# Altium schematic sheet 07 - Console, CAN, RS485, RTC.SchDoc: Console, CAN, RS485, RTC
size A3; PageSetup: Record=PageOptions¦CenterHorizontal=True¦CenterVertical=True¦PrintScale=0.70¦XCorrection=1.00¦YCorrection=1.00¦PrintKind=0¦BorderSize=5000000¦LeftOffset=0¦BottomOffset=0¦Orientation=2¦PaperLength=4200¦PaperWidth=2970¦Scale=100¦PaperSource=7¦PrintQuality=600¦MediaType=1¦DitherType=10¦PaperKind=A4¦PrintScaleMode=1; Author: Juan Anzola; SheetNumber: 7; SheetTotal: 20
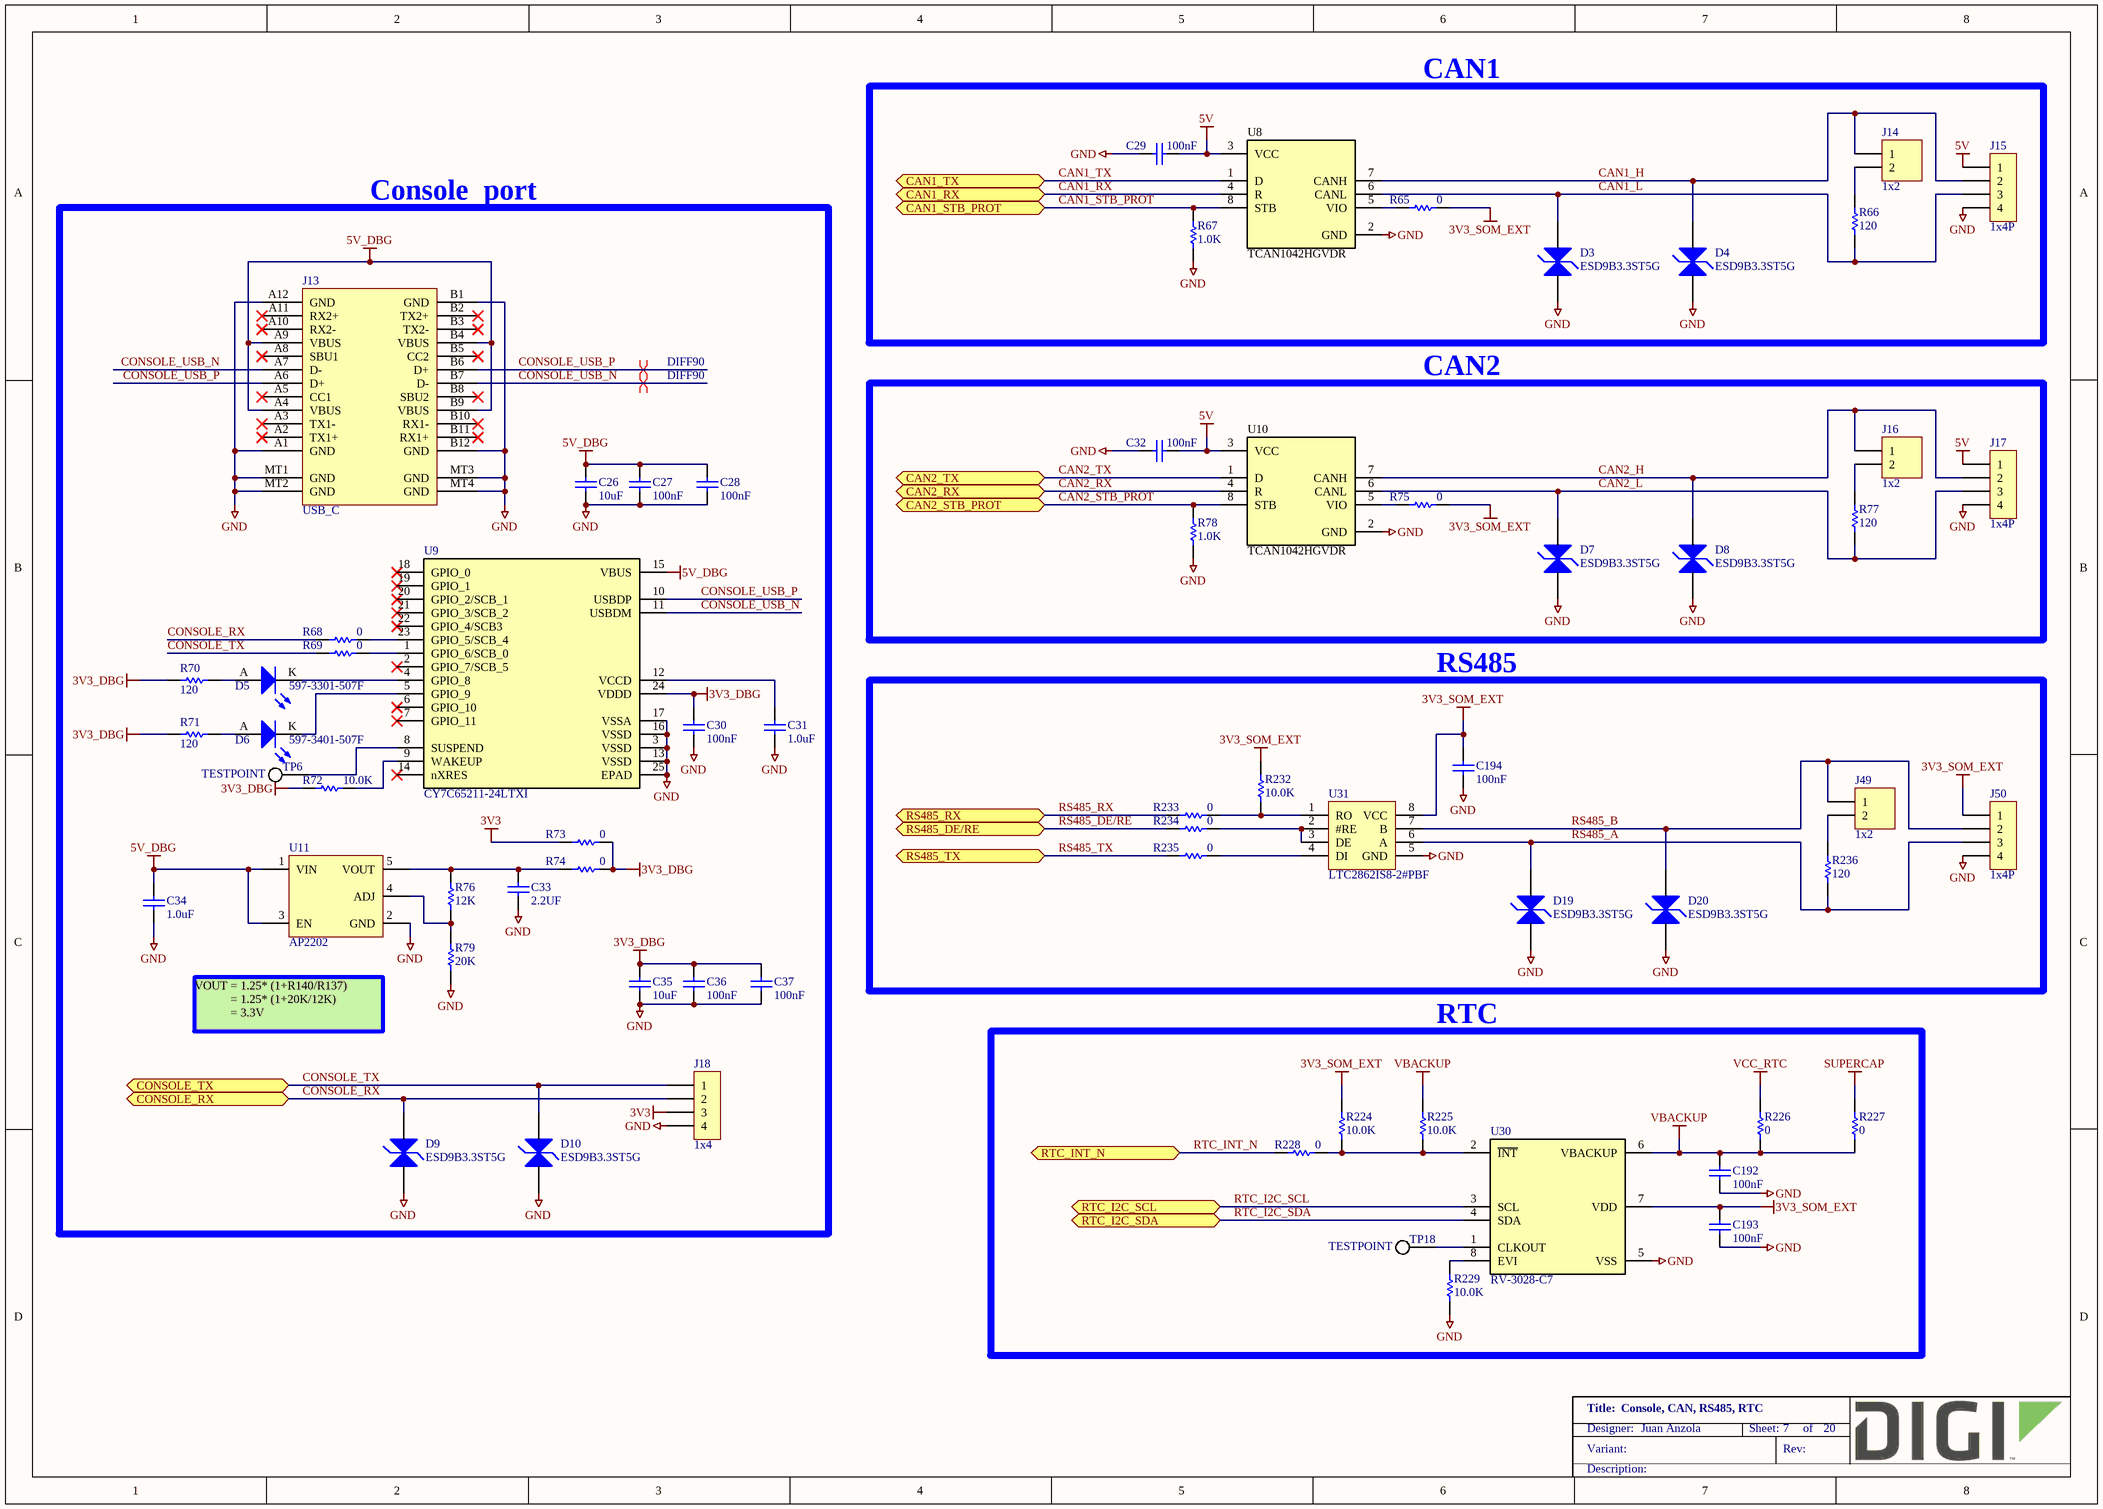
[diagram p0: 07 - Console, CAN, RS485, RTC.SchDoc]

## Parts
C26  10uF  [CAPC2013X135N]
C27  100nF  [CAPC1005X55N]
C28  100nF  [CAPC1005X55N]
C29  100nF  [CAPC1005X55N]
C30  100nF  [CAPC1005X55N]
C31  1.0uF  [CAPC1005X55N]
C32  100nF  [CAPC1005X55N]
C33  2.2UF  [CAPC1608X90N]
C34  1.0uF  [CAPC1005X55N]
C35  10uF  [CAPC2013X135N]
C36  100nF  [CAPC1005X55N]
C37  100nF  [CAPC1005X55N]
C192  100nF  [CAPC1005X55N]
C193  100nF  [CAPC1005X55N]
C194  100nF  [CAPC1005X55N]
D3  ESD9B3.3ST5G  [SODFL1006X43AN12]
D4  ESD9B3.3ST5G  [SODFL1006X43AN12]
D5  597-3301-507F  [LEDM3020X130N_GREEN]
D6  597-3401-507F  [LEDM3020X130N_YELLOW]
D7  ESD9B3.3ST5G  [SODFL1006X43AN12]
D8  ESD9B3.3ST5G  [SODFL1006X43AN12]
D9  ESD9B3.3ST5G  [SODFL1006X43AN12]
D10  ESD9B3.3ST5G  [SODFL1006X43AN12]
D19  ESD9B3.3ST5G  [SODFL1006X43AN12]
D20  ESD9B3.3ST5G  [SODFL1006X43AN12]
J13  USB_C  [MOLEX_201267-0005]
J14  1x2  [FCI_68002-102HLF]
J15  1x4P  [P4_STR_C2.54_H5.84]
J16  1x2  [FCI_68002-102HLF]
J17  1x4P  [P4_STR_C2.54_H5.84]
J18  1x4  [MOLEX_53047-0410]
J49  1x2  [FCI_68002-102HLF]
J50  1x4P  [P4_STR_C2.54_H5.84]
R65  0  [RESC1005X40N]
R66  120  [RESC1005X40N]
R67  1.0K  [RESC1005X40N]
R68  0  [RESC1005X40N]
R69  0  [RESC1005X40N]
R70  120  [RESC1005X40N]
R71  120  [RESC1005X40N]
R72  10.0K  [RESC1005X40N]
R73  0  [RESC1609X55N]
R74  0  [RESC1609X55N]
R75  0  [RESC1005X40N]
R76  12K  [RESC1609X55N]
R77  120  [RESC1005X40N]
R78  1.0K  [RESC1005X40N]
R79  20K  [RESC1609X55N]
R224  10.0K  [RESC1005X40N]
R225  10.0K  [RESC1005X40N]
R226  0  [RESC1005X40N]
R227  0  [RESC1005X40N]
R228  0  [RESC1005X40N]
R229  10.0K  [RESC1005X40N]
R232  10.0K  [RESC1005X40N]
R233  0  [RESC1005X40N]
R234  0  [RESC1005X40N]
R235  0  [RESC1005X40N]
R236  120  [RESC1005X40N]
TP6  TESTPOINT  [TP0762]  (no BOM)
TP18  TESTPOINT  [TP0762]  (no BOM)
U8  TCAN1042HGVDR  [SOIC127P600X175-8N]
U9  CY7C65211-24LTXI  [QFN50P400X400X100-25]
U10  TCAN1042HGVDR  [SOIC127P600X175-8N]
U11  AP2202  [SOT95P280X145-5N]
U30  RV-3028-C7  [DFN_8P_RV3028C7]
U31  LTC2862IS8-2#PBF  [SOIC127P600X175-8N]

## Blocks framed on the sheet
CAN1: C29 D3 D4 J14 J15 R65-R67 U8
Console  port: C26-C28 C30 C31 C33-C37 D5 D6 D9 D10 J13 J18 R68-R74 R76 R79 TP6 U9 U11
CAN2: C32 D7 D8 J16 J17 R75 R77 R78 U10
RS485: C194 D19 D20 J49 J50 R232-R236 U31
RTC: C192 C193 R224-R229 TP18 U30

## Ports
CAN1_RX (bidir), CAN1_STB_PROT (bidir), CAN1_TX (bidir), CAN2_RX (bidir), CAN2_STB_PROT (bidir), CAN2_TX (bidir), CONSOLE_RX (bidir), CONSOLE_TX (bidir), RS485_DE/RE (bidir), RS485_RX (bidir), RS485_TX (bidir), RTC_I2C_SCL (bidir), RTC_I2C_SDA (bidir), RTC_INT_N (bidir)

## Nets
3V3: J18.3 R73.1
3V3_DBG: C30.2 C35.2 C36.2 C37.2 R70.1 R71.1 R72.2 R73.2 R74.2 U9.24(VDDD)
3V3_SOM_EXT: C193.2 C194.2 J50.1 R65.2 R75.2 R224.2 R232.2 U30.7(VDD) U31.8(VCC)
5V: C29.1 C32.1 J15.1 J17.1 U8.3(VCC) U10.3(VCC)
5V_DBG: C26.2 C27.2 C28.2 C34.1 J13.A4(VBUS) J13.A9(VBUS) J13.B4(VBUS) J13.B9(VBUS) U9.15(VBUS) U11.1(VIN) U11.3(EN)
GND: C26.1 C27.1 C28.1 C29.2 C30.1 C31.2 C32.2 C33.1 C34.2 C35.1 C36.1 C37.1 C192.1 C193.1 C194.1 D3.1 D4.1 D7.1 D8.1 D9.1 D10.1 D19.1 D20.1 J13.A1(GND) J13.A12(GND) J13.B1(GND) J13.B12(GND) J13.MT1(GND) J13.MT2(GND) J13.MT3(GND) J13.MT4(GND) J15.4 J17.4 J18.4 J50.4 R67.1 R78.1 R79.1 R229.1 U8.2(GND) U9.3(VSSD) U9.13(VSSD) U9.16(VSSD) U9.17(VSSA) U9.25(EPAD) U10.2(GND) U11.2(GND) U30.5(VSS) U31.5(GND)
SUPERCAP: R227.2
VBACKUP: C192.2 R225.2 R226.1 R227.1 U30.6(VBACKUP)
VCC_RTC: R226.2
CAN1_H: D4.2 J14.1 J15.2 U8.7(CANH)
CAN1_L: D3.2 J15.3 R66.1 U8.6(CANL)
CAN1_RX: U8.4(R) ; port CAN1_RX
CAN1_STB_PROT: R67.2 U8.8(STB) ; port CAN1_STB_PROT
CAN1_TX: U8.1(D) ; port CAN1_TX
CAN2_H: D8.2 J16.1 J17.2 U10.7(CANH)
CAN2_L: D7.2 J17.3 R77.1 U10.6(CANL)
CAN2_RX: U10.4(R) ; port CAN2_RX
CAN2_STB_PROT: R78.2 U10.8(STB) ; port CAN2_STB_PROT
CAN2_TX: U10.1(D) ; port CAN2_TX
CONSOLE_RX: D9.2 J18.2 R68.1 ; port CONSOLE_RX
CONSOLE_TX: D10.2 J18.1 R69.1 ; port CONSOLE_TX
CONSOLE_USB_N: J13.A7(D-) J13.B7(D-) U9.11(USBDM)
CONSOLE_USB_P: J13.A6(D+) J13.B6(D+) U9.10(USBDP)
RS485_A: D19.2 J50.3 R236.1 U31.6(A)
RS485_B: D20.2 J49.1 J50.2 U31.7(B)
RS485_DE/RE: R234.1 ; port RS485_DE/RE
RS485_RX: R233.1 ; port RS485_RX
RS485_TX: R235.1 ; port RS485_TX
RTC_I2C_SCL: U30.3(SCL) ; port RTC_I2C_SCL
RTC_I2C_SDA: U30.4(SDA) ; port RTC_I2C_SDA
RTC_INT_N: R228.1 ; port RTC_INT_N
NetC31_1: C31.1 U9.12(VCCD)
NetC33_2: C33.2 R74.1 R76.2 U11.5(VOUT)
NetD5_A: D5.A R70.2
NetD5_K: D5.K U9.4(GPIO_8)
NetD6_A: D6.A R71.2
NetD6_K: D6.K U9.5(GPIO_9)
NetJ14_2: J14.2 R66.2
NetJ16_2: J16.2 R77.2
NetJ49_2: J49.2 R236.2
NetR65_1: R65.1 U8.5(VIO)
NetR68_2: R68.2 U9.23(GPIO_5/SCB_4)
NetR69_2: R69.2 U9.1(GPIO_6/SCB_0)
NetR72_1: R72.1 U9.9(WAKEUP)
NetR75_1: R75.1 U10.5(VIO)
NetR76_1: R76.1 R79.2 U11.4(ADJ)
NetR224_1: R224.1 R225.1 R228.2 U30.2(~{INT})
NetR229_2: R229.2 U30.8(EVI)
NetR232_1: R232.1 R233.2 U31.1(RO)
NetR234_2: R234.2 U31.2(#RE) U31.3(DE)
NetR235_2: R235.2 U31.4(DI)
NetTP6_1: TP6.1 U9.8(SUSPEND)
NetTP18_1: TP18.1 U30.1(CLKOUT)

Not connected (* = marked no-connect by the designer): J13 A2(TX1+)* A3(TX1-)* A5(CC1)* A8(SBU1)* A10(RX2-)* A11(RX2+)* B2(TX2+)* B3(TX2-)* B5(CC2)* B8(SBU2)* B10(RX1-)* B11(RX1+)*; U9 2(GPIO_7/SCB_5)* 6(GPIO_10)* 7(GPIO_11)* 14(nXRES)* 18(GPIO_0)* 19(GPIO_1)* 20(GPIO_2/SCB_1)* 21(GPIO_3/SCB_2)* 22(GPIO_4/SCB3)*

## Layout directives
differential pair; differential pair class DIFF90: CONSOLE_USB_N, CONSOLE_USB_P

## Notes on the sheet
- VOUT = 1.25* (1+R140/R137)
  = 1.25* (1+20K/12K)
  = 3.3V

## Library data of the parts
C26 C35 = 1000111: CAP CER 10UF 16V 10% X5R 0805; Part_Type: Capacitor; Manufacturer: Murata; Manufacturer_Part_Number: GRM21BR61C106KE15L; Digi_PN: 14050701; Component_Life_Cycle_State: Proven; Area: 3,99; Tolerance: 10
C27 C28 C192-C194 = 1000006: CAP 100nF 16V 10% X7R 0402; Part_Type: Capacitor; Manufacturer: Murata; Manufacturer_Part_Number: GRM155R71C104KA88D; Digi_PN: 14050552; Component_Life_Cycle_State: CAD Reviewed; Area: 0,95; Tolerance: 10
C29 C32 = 1000006: CAP 100nF 16V 10% X7R 0402; Part_Type: Capacitor; Manufacturer: Murata; Manufacturer_Part_Number: GRM155R71C104KA88D; Component_Life_Cycle_State: CAD Reviewed; Area: 0.95; Project: KITT; Tolerance: 10; Digi_PN: 14050552
C30 C36 C37 = 1000006: CAP 100nF 16V 10% X7R 0402; Part_Type: Capacitor; Manufacturer: Murata; Manufacturer_Part_Number: GRM155R71C104KA88D; Digi_PN: 14050552; Component_Life_Cycle_State: CAD Reviewed; Area: 0,95; Project: KITT; Tolerance: 10
C31 C34 = 1000073: CAP CER 1UF 6.3V 20% X5R 0402; Part_Type: Capacitor; Manufacturer: Murata; Manufacturer_Part_Number: GRM155R60J105ME19D; Digi_PN: 14050543; Component_Life_Cycle_State: Proven; Area: 0.95; Project: Adjustable Foundation
C33 = 1001303: CAP CER 2.2UF 16V 10% X5R 0603; Part_Type: Capacitor; Manufacturer: TDK Corporation; Manufacturer_Part_Number: C1608X5R1C225K080AB; Digi_PN: 14050730; Component_Life_Cycle_State: Reviewed; Area: 2,27
D3 D4 D7 D8 D19 D20 = 1001637: TVS DIODE 3.3VWM SOD923; Part_Type: Diodes; Manufacturer: On Semiconductor; Digi_PN: 17050883; Component_Life_Cycle_State: Reviewed; Area: 1,01
D5 = 1001189: LED GREEN 573NM 1208 SMD; Manufacturer: Dialight; Note: 17050846 = Digi PN for GE WDNU II; Digi_PN: 17050183; Component_Life_Cycle_State: Reviewed; Area: 6
D6 = 1001188: LED YELLOW 588NM 1208 SMD; Manufacturer: Dialight; Note: 17050842 = Digi No. for GE WDNU; Digi_PN: 17050387; Component_Life_Cycle_State: Reviewed; Area: 6
D9 D10 = 1001637: TVS DIODE 3.3VWM SOD923; Part_Type: Diodes; Manufacturer: On Semiconductor; Digi_PN: 17050883; Component_Life_Cycle_State: Reviewed; Area: 1,01; Project: CareTaker IV
J13 = 1002675: USB 3.1 SHIELDED I/O RECP TYPE C GEN2; Part_Type: Connector; Manufacturer: Molex; Manufacturer_Part_Number: 201267-0005; Digi_PN: 18000775; Component_Life_Cycle_State: Reviewed; Area: 91,35
J14 J16 J49 = 1001128: CONN HEADER 2POS .100" SGL GOLD; Part_Type: Connector; Manufacturer: Samtec; Manufacturer_Part_Number: TSW-102-07-G-S; Digi_PN: 00120002; Component_Life_Cycle_State: Reviewed; Area: 12,9032
J15 J17 J50 = 1002860: CONN HEADER VERT 4POS 2.54MM; Part_Type: Connector; Manufacturer: Samtec; Manufacturer_Part_Number: TSW-104-07-G-S; Digi_PN: 00120004; Component_Life_Cycle_State: Pending
J18 = 1001137: CONN HEADER 4POS 1.25MM VERT TIN; Part_Type: Connector; Manufacturer: Molex; Manufacturer_Part_Number: 53047-0410; Digi_PN: 18050344; Component_Life_Cycle_State: Reviewed; Area: 21,6
R65 R69 R75 = 1000076: RES 0.0 OHM 1/10W 0402 SMD; Part_Type: Resistor; Manufacturer: Panasonic - ECG; Manufacturer_Part_Number: ERJ-2GE0R00X; Component_Life_Cycle_State: Proven; Area: 0.95; Project: Adjustable Foundation; Power_WV_SRF: 10; Digi_PN: 13050387
R66 R70 R71 R77 = 1001158: RES 120 OHM 1/16W 1% 0402 SMD; Part_Type: Resistor; Manufacturer: Yageo; Manufacturer_Part_Number: RC0402FR-07120RL; Digi_PN: 13050832; Component_Life_Cycle_State: Reviewed; Area: 0.95; Project: CCWMX6_SBC board; Note: 13051102 = Digi No. for GE WDNU
R67 R78 = 1000079: RES 1.00K OHM 1/10W 1% 0402 SMD; Part_Type: Resistor; Manufacturer: Panasonic - ECG; Manufacturer_Part_Number: ERJ-2RKF1001X; Digi_PN: 13051085; Component_Life_Cycle_State: Proven; Area: 0,95; Project: Adjustable Foundation; Power_WV_SRF: 10
R68 R226-R228 R233-R235 = 1000076: RES 0.0 OHM 1/10W 0402 SMD; Part_Type: Resistor; Manufacturer: Panasonic - ECG; Manufacturer_Part_Number: ERJ-2GE0R00X; Digi_PN: 13050387; Component_Life_Cycle_State: Proven; Area: 0,95; Power_WV_SRF: 10
R72 = 1000537: RES 10.0K OHM 1/10W 1% 0402 SMD; Part_Type: Resistor; Manufacturer: Panasonic - ECG; Manufacturer_Part_Number: ERJ-2RKF1002X; Component_Life_Cycle_State: CAD Reviewed; Area: 0.95; Project: KITT; Power_WV_SRF: 100; Digi_PN: 13051084
R73 R74 = 1000208: RES 0.0 OHM 1/10W 0603; Part_Type: Resistor; Manufacturer: Panasonic - ECG; Manufacturer_Part_Number: ERJ-3GEY0R00V; Note: 13051103 = Digi No. for GE WDNU; Digi_PN: 13050568; Component_Life_Cycle_State: Reviewed; Area: 2,5; Voltage: 75V
R76 = 1001200: RES 12.0K OHM 1/10W 1% 0603 SMD; Part_Type: Resistor; Manufacturer: Yageo; Manufacturer_Part_Number: RC0603FR-0712KL; Digi_PN: 13050531; Component_Life_Cycle_State: Reviewed; Area: 2,5; Power_WV_SRF: 100; Tolerance: 1
R79 = 1000142: RES 20K OHM 1/10W 5% 0603 SMD; Part_Type: Resistor; Manufacturer: Panasonic - ECG; Manufacturer_Part_Number: ERJ-3GEYJ203V; Digi_PN: 13050013; Component_Life_Cycle_State: Reviewed; Area: 2,5; Power_WV_SRF: 100; Tolerance: 5
R224 R225 R229 R232 = 1000537: RES 10.0K OHM 1/10W 1% 0402 SMD; Part_Type: Resistor; Manufacturer: Panasonic - ECG; Manufacturer_Part_Number: ERJ-2RKF1002X; Digi_PN: 13051084; Component_Life_Cycle_State: CAD Reviewed; Area: 0,95; Power_WV_SRF: 100
R236 = 1001158: RES 120 OHM 1/16W 1% 0402 SMD; Part_Type: Resistor; Manufacturer: Yageo; Manufacturer_Part_Number: RC0402FR-07120RL; Note: 13051102 = Digi No. for GE WDNU; Digi_PN: 13050832; Component_Life_Cycle_State: Reviewed; Area: 0,95
TP6 = CAD0011: TEST POINT 30mil PAD SMT; Component_Life_Cycle_State: Reviewed; Area: 0.58; Project: CLC
TP18 = CAD0011: TEST POINT 30MIL PAD SMT; Component_Life_Cycle_State: Reviewed; Area: 0,58
U8 U10 = 1002681: IC CAN TRANSEIVER HS 8SOIC; Manufacturer: Texas Instruments; Digi_PN: 16000166; Component_Life_Cycle_State: Pending; Area: 20; Project: DIGI CC8X SOM
U9 = 1002827: IC USB TO SERIAL BRIDGE 24QFN; Manufacturer: Cypress Semiconductor; Digi_PN: 16000439; Component_Life_Cycle_State: Pending
U11 = 1001979: IC REG LDO ADJ 0.15A SOT25; Part_Type: Regulator; Manufacturer: Diodes, Inc.; Manufacturer_Part_Number: AP2202K-ADJTRG1; Digi_PN: 17050874; Component_Life_Cycle_State: Reviewed; Area: 14,92
U30 = 1002829: SMIC, RTC, I2C, RV-3028-C7, 45n@3V, DFN-8, -40/+85°C; Manufacturer_Name: Micro Crystal AG; Manufacturer_Part_Number: RV-3028-C7 32.768kHz 1ppm TA QC; Part_Type: IC; Manufacturer: Micro Commercial Co; Digi_PN: 16000441; Component_Life_Cycle_State: Created; Area: 4,8
U31 = 1001420: IC TRANSCEIVER RS485 8-SOIC; Manufacturer: Linear Technology; Digi_PN: 16052092; Component_Life_Cycle_State: Reviewed; Area: 34,75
